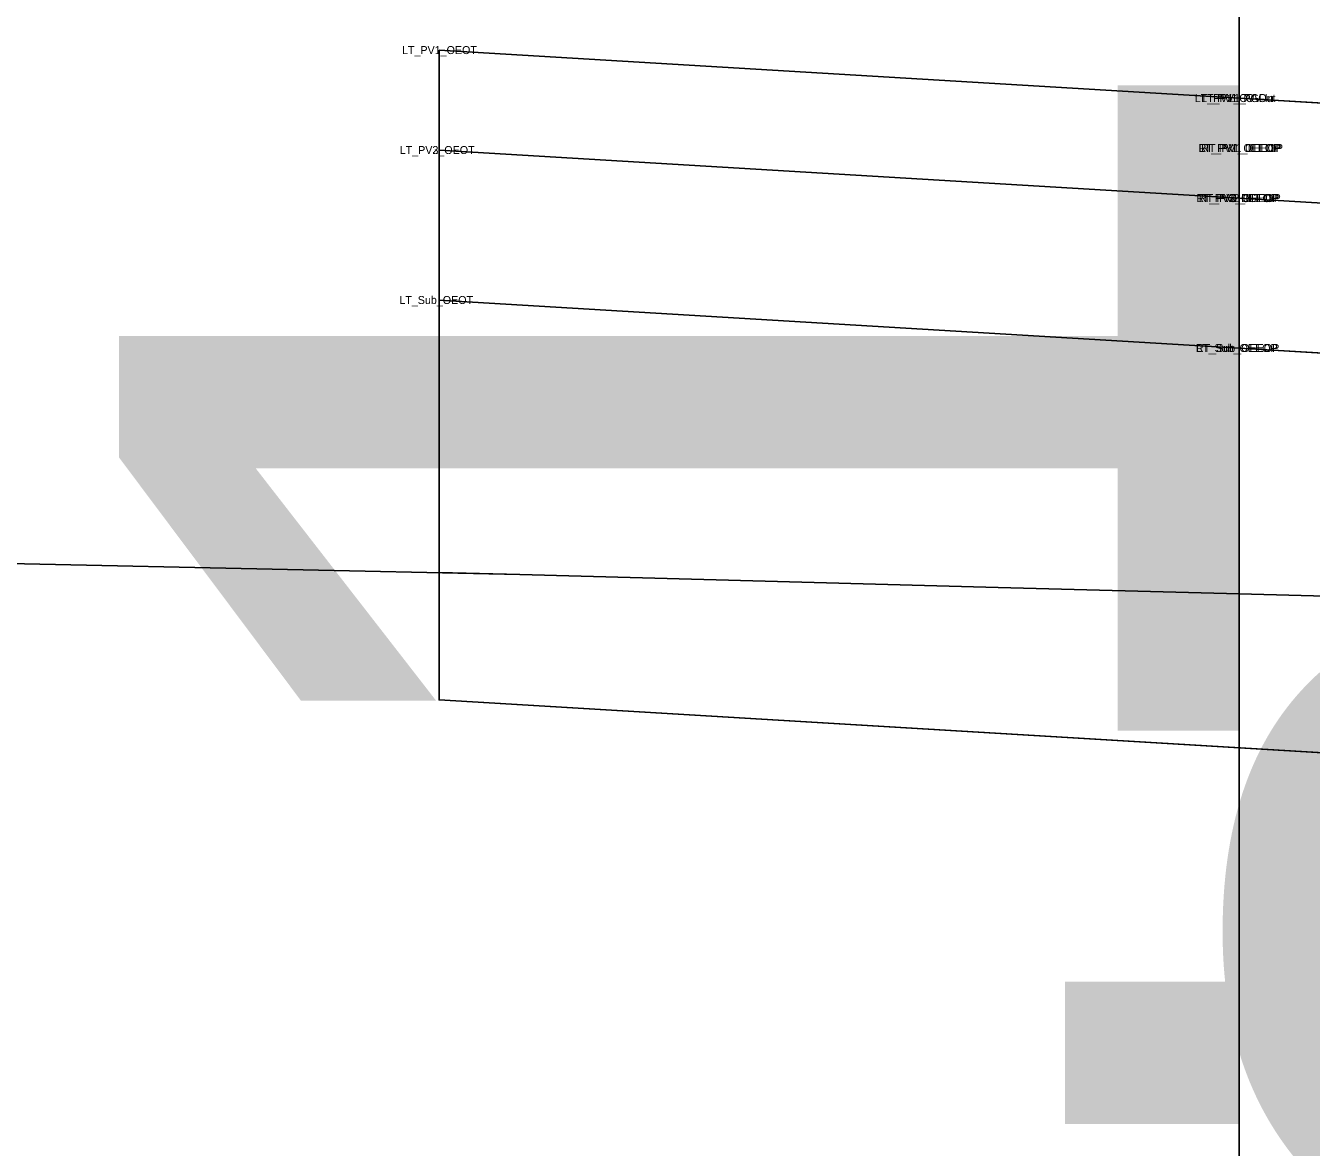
# Model space of a CAD drawing. Extents: x -516 to 303, y -10 to 5017.
# Drawn here: x 146.967 to 150.18, y 2006.522 to 2009.327 of the extents above; entities that cross this region are included whole.
import ezdxf

# ---------------------------------------------------------------- set-up
doc = ezdxf.new("R2010")
doc.units = 0
for name, color, linetype in [('Exist Cross Section Cell', 7, 'Continuous'), ('Exist XS Ground Line', 7, 'Continuous'), ('Prop CMT Pvmt Course 1', 7, 'Continuous'), ('Prop CMT Pvmt Course 2', 7, 'Continuous'), ('Prop CMT Pvmt Course 3', 7, 'Continuous'), ('Prop CMT Pvmt Surface', 7, 'Continuous'), ('Prop CMT Subgrade Earthwork', 7, 'Continuous'), ('Prop Road Sect_ Misc - Drafting Aid (solid line)', 7, 'Continuous'), ('Prop Road Sect_ Recs - UC Shallow (Outline)', 7, 'Continuous'), ('Prop Road Sect_ Recs - UC Shallow (Pattern)', 7, 'Continuous'), ('Scratch_Level_0', 7, 'Continuous')]:
    doc.layers.add(name, color=color, linetype=linetype)

msp = doc.modelspace()

# ---------------------------------------------------------------- linework, layer by layer
at = {"layer": 'Exist Cross Section Cell'}
msp.add_line((150, 2000), (150, 2030.4404), dxfattribs=at)
at = {"layer": 'Exist XS Ground Line'}
msp.add_lwpolyline([(139.074, 2008.0997), (140.4171, 2008.103), (141.132, 2008.106), (143.3267, 2008.0797), (143.9958, 2008.0596), (145.6153, 2008.0126), (145.9784, 2008.006), (146.9642, 2007.9817), (148.2019, 2007.9549), (149.3973, 2007.9221), (150, 2007.906), (150.7755, 2007.8854), (153.3472, 2007.8082), (154.1183, 2007.7912), (155.9076, 2007.7453), (157.6019, 2007.6791), (158.4835, 2007.6479), (159.961, 2007.5813)], dxfattribs=at)
at = {"layer": 'Prop CMT Pvmt Course 1'}
for points in [[(150, 2009.1461), (148, 2009.2661)], [(148, 2009.2661), (148, 2009.0161)], [(150, 2009.0211), (150, 2009.1461)], [(150, 2009.1461), (162, 2008.4261)], [(150, 2008.896), (150, 2009.1461)], [(150, 2008.896), (150, 2009.0211)], [(148, 2009.0161), (150, 2008.896)], [(162, 2008.1761), (150, 2008.896)]]:
    msp.add_lwpolyline(points, dxfattribs=at)
msp.add_lwpolyline([(150, 2008.896), (150, 2009.0211), (150, 2009.0211), (150, 2008.896)], close=True, dxfattribs=at)
at = {"layer": 'Prop CMT Pvmt Course 2'}
for points in [[(148, 2009.0161), (150, 2008.896)], [(150, 2008.896), (148, 2009.0161)], [(148, 2009.0161), (148, 2009.0161)], [(150, 2008.896), (150, 2008.896)], [(162, 2008.1761), (150, 2008.896)], [(150, 2008.896), (150, 2008.896)], [(150, 2008.896), (162, 2008.1761)]]:
    msp.add_lwpolyline(points, dxfattribs=at)
at = {"layer": 'Prop CMT Pvmt Course 3'}
for points in [[(150, 2008.896), (148, 2009.0161)], [(148, 2009.0161), (148, 2008.6411)], [(150, 2008.521), (150, 2008.896)], [(150, 2008.896), (162, 2008.1761)], [(150, 2008.521), (150, 2008.896)], [(148, 2008.6411), (150, 2008.521)], [(162, 2007.8011), (150, 2008.521)]]:
    msp.add_lwpolyline(points, dxfattribs=at)
at = {"layer": 'Prop CMT Pvmt Surface'}
for p, q in [((148, 2009.2661), (148, 2008.6411)), ((150, 2009.1461), (148, 2009.2661)), ((150, 2009.1461), (150, 2009.1461)), ((150, 2009.1461), (150, 2009.1461)), ((150, 2009.1461), (162, 2008.4261))]:
    msp.add_line(p, q, dxfattribs=at)
at = {"layer": 'Prop CMT Subgrade Earthwork'}
for p, q in [((148, 2008.6411), (148, 2007.9593)), ((150, 2008.521), (148, 2008.6411)), ((150, 2008.521), (162, 2007.8011))]:
    msp.add_line(p, q, dxfattribs=at)
at = {"layer": 'Prop Road Sect_ Misc - Drafting Aid (solid line)'}
for p in [(148, 2008.6411), (162, 2006.8011)]:
    msp.add_line(p, (148, 2007.6411), dxfattribs=at)
at = {"layer": 'Prop Road Sect_ Recs - UC Shallow (Outline)'}
msp.add_lwpolyline([(148, 2007.6411), (148, 2007.9593), (148.2019, 2007.9549), (149.3973, 2007.9221), (150, 2007.906), (150.7755, 2007.8854), (153.3472, 2007.8082), (154.1183, 2007.7912), (155.9076, 2007.7453), (157.6019, 2007.6791), (158.4835, 2007.6479), (159.961, 2007.5813), (161.0579, 2007.5364), (161.7106, 2007.5109), (163.7403, 2007.435), (164.3584, 2007.4133), (164.8981, 2007.3863), (165.9538, 2007.3364), (166.2649, 2007.3278), (166.2649, 2006.6052), (165.2649, 2006.6052), (162, 2006.8011)], close=True, dxfattribs=at)
at = {"layer": 'Prop Road Sect_ Recs - UC Shallow (Pattern)'}
msp.add_lwpolyline([(162, 2006.8011), (165.2649, 2006.6052), (166.2649, 2006.6052), (166.2649, 2007.3278), (165.9538, 2007.3364), (164.8981, 2007.3863), (164.3584, 2007.4133), (163.7403, 2007.435), (161.7106, 2007.5109), (161.0579, 2007.5364), (159.961, 2007.5813), (158.4835, 2007.6479), (157.6019, 2007.6791), (155.9076, 2007.7453), (154.1183, 2007.7912), (153.3472, 2007.8082), (150.7755, 2007.8854), (150, 2007.906), (149.3973, 2007.9221), (148.2019, 2007.9549), (148, 2007.9593), (148, 2007.6411), (162, 2006.8011)], dxfattribs=at)

# ---------------------------------------------------------------- texts
at = {"layer": 'Exist Cross Section Cell'}
for s, p in [('E 2266393.4948', (152.8, 1990)), ('N 511365.1629', (150, 1990))]:
    msp.add_text(s, height=2.8, rotation=90, dxfattribs=at).set_placement(p)
at = {"layer": 'Scratch_Level_0'}
for s, p in [('LT_PV1_OEOT', (147.9074, 2009.2561)), ('LT_PV1_OV-Out', (149.8885, 2009.1361)), ('LT_PV1_OV-In', (149.9047, 2009.1361)), ('PV1_PGL', (149.9447, 2009.1361)), ('LT_PV3_OEOT', (147.9017, 2009.0061)), ('LT_PV2_OEOT', (147.9017, 2009.0061)), ('RT_PV1_OEEOP', (149.8983, 2009.0111)), ('LT_PV1_OEEOP', (149.8987, 2009.0111)), ('RT_PV1_IEEOP', (149.9047, 2009.0111)), ('RT_PV2_OEEOP', (149.8926, 2008.886)), ('RT_PV3_OEEOP', (149.8926, 2008.886)), ('LT_PV2_OEEOP', (149.8931, 2008.886)), ('LT_PV3_OEEOP', (149.8931, 2008.886)), ('RT_PV2_IEEOP', (149.8991, 2008.886)), ('PV2_PGL', (149.9391, 2008.886)), ('LT_Sub_OEOT', (147.9008, 2008.6311)), ('RT_Sub_OEEOP', (149.8917, 2008.511)), ('LT_Sub_OEEOP', (149.8921, 2008.511))]:
    msp.add_text(s, height=0.02, dxfattribs=at).set_placement(p)

doc.saveas('drawing.dxf')
